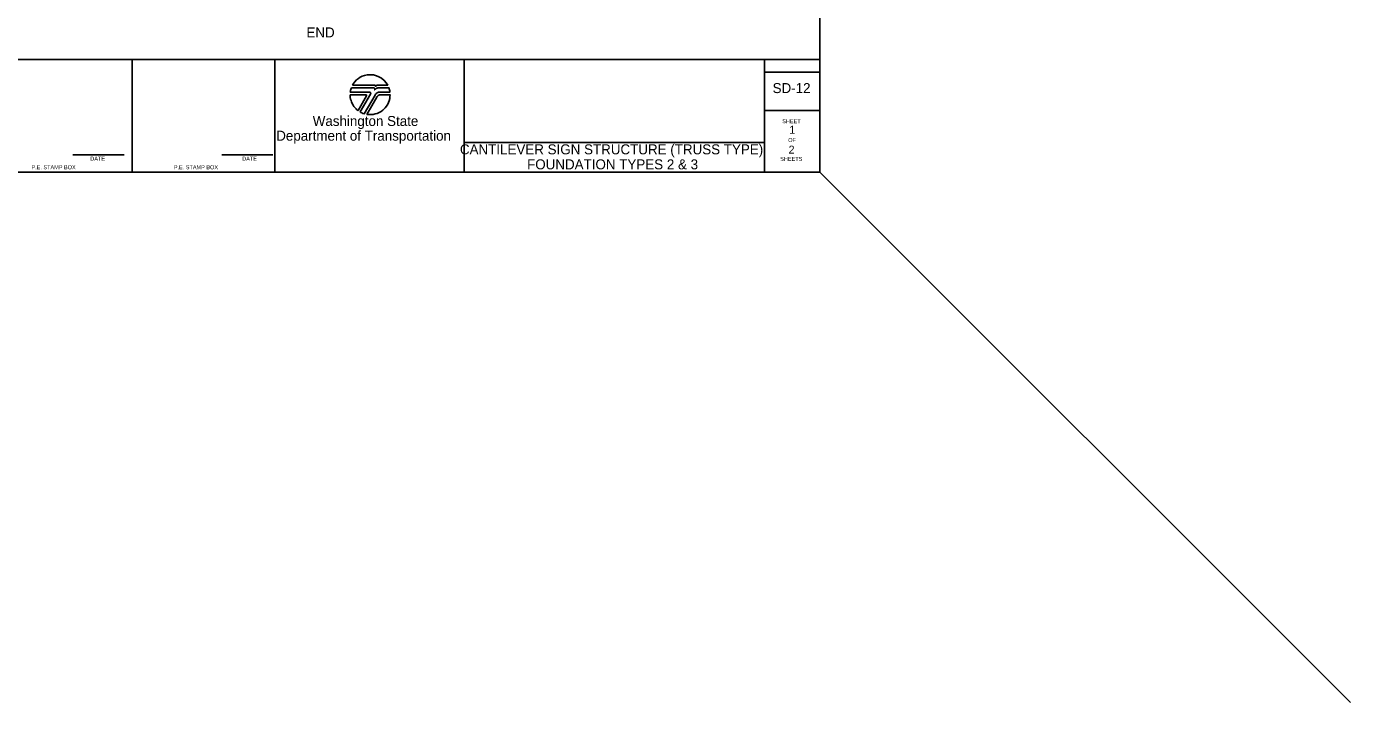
# Model space of a CAD drawing. Extents: x 99862 to 104211, y 98939 to 105076.
# Drawn here: x 101564 to 104211, y 98939 to 100291 of the extents above; entities that cross this region are included whole.
import ezdxf

# ---------------------------------------------------------------- set-up
doc = ezdxf.new("R2010")
doc.units = 0
for name, color, linetype in [('Level 1', 7, 'Continuous'), ('Level 20', 7, 'Continuous'), ('Level 60', 7, 'Continuous')]:
    doc.layers.add(name, color=color, linetype=linetype)

msp = doc.modelspace()

# ---------------------------------------------------------------- linework, layer by layer
at = {"layer": 'Level 1'}
msp.add_line((103150, 100000), (104210.7, 98939.3), dxfattribs=at)
at = {"layer": 'Level 60'}
for p, q in [((103150, 100000), (103150, 102075)), ((100000, 100225), (103150, 100225)), ((101775.1, 100000), (101775.1, 100225)), ((102060.1, 100225), (102060.1, 100000)), ((102439.1, 100225), (102439.1, 100000)), ((103039.1, 100225), (103039.1, 100000)), ((103039.1, 100200), (103150, 100200)), ((103039.1, 100123.4), (103150, 100123.4)), ((102439.1, 100059.1), (103039.1, 100059.1)), ((101656.7, 100034.6), (101759, 100034.6)), ((101954.4, 100034.6), (102056.6, 100034.6)), ((100000, 100000), (103150, 100000))]:
    msp.add_line(p, q, dxfattribs=at)
for points in [[(102215.6, 100173.9), (102259.9, 100173.9), (102260.7, 100173.7), (102261.4, 100173.2), (102261.7, 100172.6), (102261.7, 100172), (102261.5, 100171.2), (102262.3, 100172.2), (102263.5, 100173.1), (102265.2, 100173.8), (102266.4, 100173.9), (102285.9, 100173.9), (102283, 100178.5), (102278.9, 100183.3), (102273.7, 100187.6), (102268.3, 100190.8), (102263.3, 100192.8), (102257.6, 100194.2), (102251.6, 100194.8), (102245.1, 100194.4), (102239.7, 100193.3), (102235.1, 100191.6), (102231.1, 100189.6), (102227.3, 100187.2), (102223.7, 100184.3), (102219.8, 100180.1), (102217.5, 100176.9)], [(102215.6, 100173.9), (102259.9, 100173.9), (102260.7, 100173.7), (102261.4, 100173.2), (102261.7, 100172.6), (102261.7, 100172), (102261.5, 100171.2), (102262.3, 100172.2), (102263.5, 100173.1), (102265.2, 100173.8), (102266.4, 100173.9), (102285.9, 100173.9), (102283, 100178.5), (102278.9, 100183.3), (102273.7, 100187.6), (102268.3, 100190.8), (102263.3, 100192.8), (102257.6, 100194.2), (102251.6, 100194.8), (102245.1, 100194.4), (102239.7, 100193.3), (102235.1, 100191.6), (102231.1, 100189.6), (102227.3, 100187.2), (102223.7, 100184.3), (102219.8, 100180.1), (102217.5, 100176.9)], [(102213.3, 100168.7), (102257.2, 100168.7), (102257.9, 100168.6), (102258.5, 100168.4), (102258.9, 100168.2), (102259.2, 100167.9), (102259.7, 100167.3), (102260, 100166.6), (102260.2, 100165.9), (102260.1, 100165.2), (102260, 100164.7), (102259.7, 100164.2), (102260.2, 100164.9), (102261.1, 100165.9), (102262.1, 100166.8), (102263.4, 100167.6), (102264.6, 100168.1), (102266.5, 100168.6), (102269.2, 100168.7), (102288.3, 100168.7), (102289.1, 100166.2), (102289.6, 100164.5), (102290, 100162.7), (102290.3, 100160.9), (102290.4, 100160.1), (102272, 100160.1), (102269.5, 100160), (102267.7, 100159.7), (102265.2, 100158.7), (102263.2, 100157.2), (102261.8, 100155.7), (102260.6, 100153.7), (102239.1, 100116.6), (102236.5, 100117.5), (102234.2, 100118.5), (102232.2, 100119.5), (102230.7, 100120.3), (102251.5, 100156.1), (102251.9, 100157.4), (102251.6, 100158.6), (102250.7, 100159.6), (102249.9, 100160), (102249.3, 100160.1), (102211.2, 100160.1), (102211.6, 100162.6), (102211.8, 100163.9), (102212.2, 100165.3), (102212.7, 100167)], [(102210.8, 100154.8), (102242.3, 100154.8), (102242.7, 100154.8), (102243.2, 100154.6), (102243.5, 100154.4), (102243.7, 100154.1), (102243.9, 100153.7), (102243.9, 100153.3), (102243.9, 100152.9), (102243.7, 100152.4), (102226.6, 100123), (102224.5, 100124.7), (102222.6, 100126.5), (102220.7, 100128.5), (102218.3, 100131.5), (102216.6, 100134.1), (102215, 100137), (102213.6, 100140.2), (102212.6, 100143), (102211.8, 100146), (102211.2, 100149), (102210.9, 100152)], [(102244.2, 100115.4), (102264.2, 100150), (102264.8, 100150.9), (102265.4, 100151.6), (102266.3, 100152.5), (102267.2, 100153.2), (102268.3, 100153.8), (102269.5, 100154.3), (102270.8, 100154.6), (102271.5, 100154.7), (102272.4, 100154.7), (102290.8, 100154.7), (102290.5, 100150.3), (102290, 100146.9), (102288.8, 100142.5), (102287.6, 100139.3), (102286, 100135.9), (102283.5, 100131.9), (102280.8, 100128.4), (102278.9, 100126.4), (102276.1, 100123.9), (102272.7, 100121.4), (102268.7, 100119.1), (102265, 100117.5), (102260.9, 100116.2), (102256.9, 100115.3), (102252.4, 100114.9), (102249.2, 100114.9), (102246.3, 100115.1)]]:
    msp.add_lwpolyline(points, close=True, dxfattribs=at)

# ---------------------------------------------------------------- texts
at = {"layer": 'Level 20'}
for s, height, p in [('END', 20, (102123.5, 100269.3)), ('SD-12', 20, (103055.4, 100158)), ('1', 16, (103088.8, 100076.7)), ('CANTILEVER SIGN STRUCTURE (TRUSS TYPE)', 20, (102430.3, 100035.5)), ('2', 16, (103087.3, 100036.9)), ('FOUNDATION TYPES 2 & 3', 20, (102564.6, 100005.5))]:
    msp.add_text(s, height=height, dxfattribs=at).set_placement(p)
at = {"layer": 'Level 60'}
for s, height, p in [('Washington State', 19.999, (102136.1, 100092.2)), ('SHEET', 8, (103074.6, 100097.8)), ('Department of Transportation', 19.999, (102063.1, 100062.8)), ('OF', 8, (103086.6, 100060.1)), ('DATE', 8.03, (101691.4, 100022.8)), ('DATE', 8.03, (101995.1, 100022.8)), ('SHEETS', 8, (103070.6, 100022.4)), ('P.E. STAMP BOX', 8, (101573.8, 100005.7)), ('P.E. STAMP BOX', 8, (101858.4, 100005.7))]:
    msp.add_text(s, height=height, dxfattribs=at).set_placement(p)

doc.saveas('drawing.dxf')
